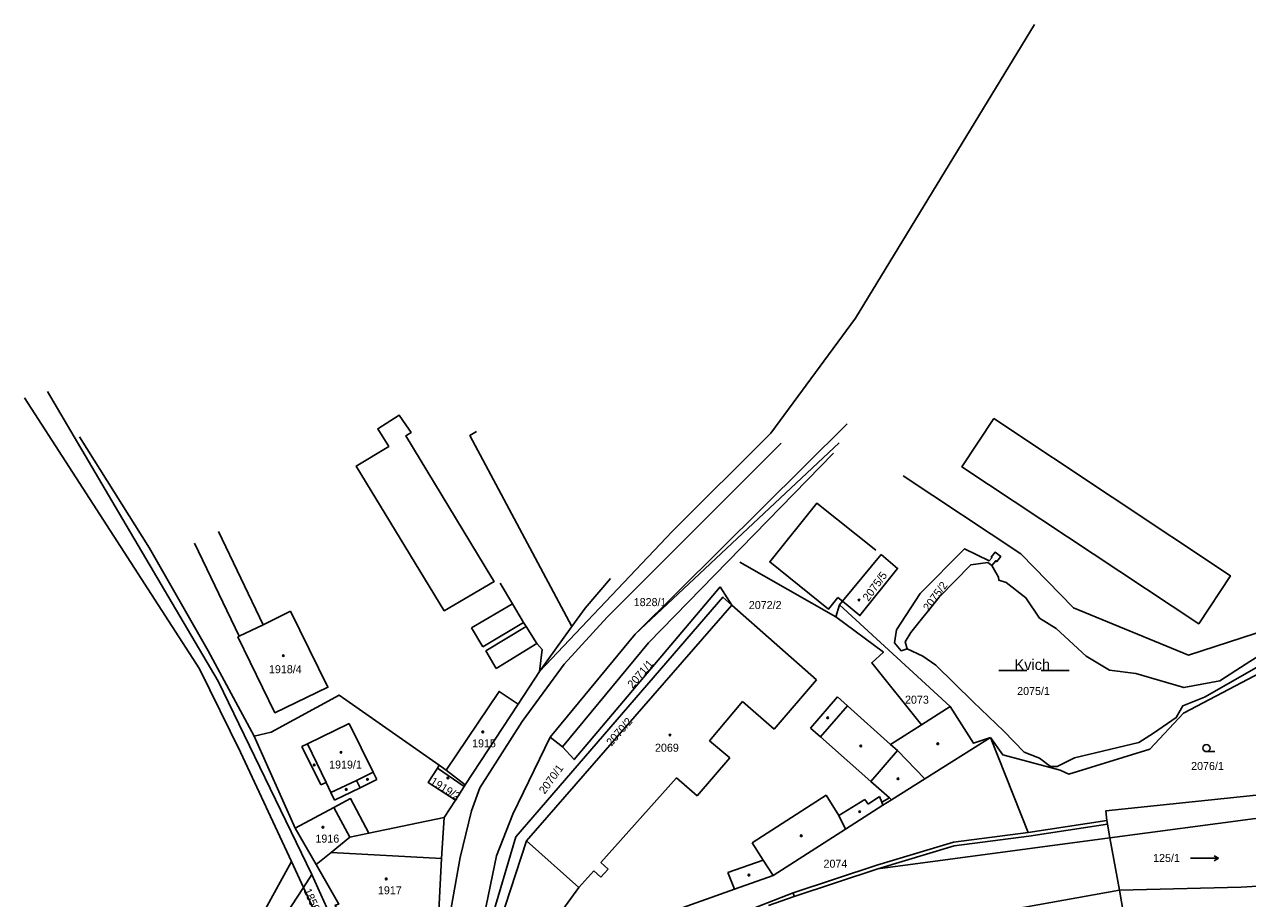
# Model space of a CAD drawing. Extents: x -783716 to -783033, y -1065203 to -1064697.
# Drawn here: x -783565.5 to -783305.8, y -1064883 to -1064697.4 of the extents above; entities that cross this region are included whole.
import ezdxf

# ---------------------------------------------------------------- set-up
doc = ezdxf.new("R2010")
doc.units = 0
for name, color, linetype in [('Budovy', 7, 'Continuous'), ('Doplňkové značky', 7, 'Continuous'), ('Doplňující texty', 7, 'Continuous'), ('Kultury', 7, 'Continuous'), ('Stromy_porost', 7, 'Continuous'), ('Značky IS', 7, 'Continuous')]:
    doc.layers.add(name, color=color, linetype=linetype)

msp = doc.modelspace()

# ---------------------------------------------------------------- linework, layer by layer
at = {"layer": 'Budovy'}
for p, q in [((-783514.83, -1064824.85), (-783524.27, -1064805.09)), ((-783529.39, -1064807.57), (-783519.89, -1064827.32)), ((-783393.24, -1064823.15), (-783413.58, -1064811.55)), ((-783391.81, -1064819.86), (-783383.6, -1064809.96)), ((-783415.27, -1064820.68), (-783417.8, -1064816.8)), ((-783391.81, -1064819.86), (-783392.77, -1064819.08)), ((-783514.83, -1064824.85), (-783509.01, -1064822.01)), ((-783393.24, -1064823.15), (-783392.46, -1064820.64)), ((-783392.46, -1064820.64), (-783391.81, -1064819.86)), ((-783368.94, -1064842.22), (-783392.46, -1064820.64)), ((-783519.89, -1064827.32), (-783514.83, -1064824.85)), ((-783520.18, -1064827.46), (-783519.89, -1064827.32)), ((-783456.16, -1064834.79), (-783449.25, -1064825.27)), ((-783456.16, -1064834.79), (-783460.7, -1064841.72)), ((-783460.7, -1064841.72), (-783471.91, -1064858.83)), ((-783508, -1064868.04), (-783516.73, -1064848.53)), ((-783352.38, -1064869), (-783360.4, -1064848.81)), ((-783508.82, -1064875.14), (-783519.64, -1064851.88)), ((-783477.44, -1064854.69), (-783475.98, -1064855.72)), ((-783475.98, -1064855.72), (-783471.91, -1064858.83)), ((-783499.8, -1064863.65), (-783508, -1064868.04)), ((-783473.99, -1064862.07), (-783476.38, -1064865.8)), ((-783503.56, -1064875.78), (-783508, -1064868.04)), ((-783523.1, -1064901.15), (-783508.82, -1064875.14)), ((-783508.82, -1064875.14), (-783506.26, -1064880.64)), ((-783506.26, -1064880.64), (-783504.45, -1064877.9)), ((-783506.26, -1064880.64), (-783502.83, -1064888))]:
    msp.add_line(p, q, dxfattribs=at)
for points in [[(-783351, -1064697.43), (-783389.01, -1064759.81), (-783407.01, -1064784.21), (-783427.95, -1064805.07), (-783448.49, -1064826.71), (-783456.16, -1064834.79)], [(-783560.59, -1064775.38), (-783546.25, -1064799.74), (-783524.35, -1064836.82), (-783504.45, -1064877.9)], [(-783519.64, -1064851.88), (-783528.32, -1064834.2), (-783565.5, -1064776.71)], [(-783484.49, -1064782.45), (-783483.39, -1064784.05), (-783484.51, -1064784.74), (-783466.28, -1064814.88), (-783465.78, -1064815.71), (-783476.35, -1064821.9), (-783495.05, -1064791.19), (-783488.16, -1064787), (-783490.49, -1064783.25), (-783485.91, -1064780.4), (-783484.49, -1064782.45)], [(-783453.88, -1064848.76), (-783435.82, -1064826.87), (-783390.82, -1064782.2)], [(-783359.63, -1064781.08), (-783309.44, -1064814.45), (-783316.16, -1064824.65), (-783366.43, -1064791.34), (-783359.63, -1064781.08)], [(-783516.73, -1064848.53), (-783526.51, -1064830.41), (-783538.93, -1064808.62), (-783553.79, -1064784.98)], [(-783449.25, -1064825.27), (-783470.93, -1064784.71), (-783469.54, -1064783.82)], [(-783378.92, -1064793.24), (-783353.96, -1064809.78), (-783342.78, -1064821.3), (-783318.3, -1064831.29), (-783298.49, -1064824.89)], [(-783392.77, -1064819.08), (-783394.74, -1064821.54), (-783407.26, -1064811.52), (-783397.23, -1064799.02), (-783384.7, -1064809.03)], [(-783360.1, -1064812.31), (-783359.24, -1064811.26), (-783359.01, -1064811.44), (-783358.2, -1064810.39), (-783359.38, -1064809.48), (-783360.21, -1064810.49), (-783360.05, -1064810.59), (-783360.62, -1064811.26), (-783365.9, -1064808.72), (-783375.28, -1064818.25), (-783380.3, -1064825.94), (-783380.77, -1064828.67), (-783379.36, -1064830.4), (-783378.03, -1064829.99)], [(-783383.6, -1064809.96), (-783380.09, -1064812.91), (-783388.1, -1064822.9), (-783391.81, -1064819.86)], [(-783360.1, -1064812.31), (-783360.93, -1064811.63), (-783364.56, -1064812.11), (-783371.25, -1064819.01), (-783377.31, -1064826.48), (-783378.51, -1064828.46), (-783378.03, -1064829.99)], [(-783298.02, -1064828.1), (-783306.05, -1064833.18), (-783311.65, -1064836.74), (-783319.29, -1064838.21), (-783322.68, -1064837.19), (-783329.49, -1064835.23), (-783335.08, -1064834.54), (-783340.03, -1064831.54), (-783346.44, -1064825.64), (-783349.95, -1064823.46), (-783352.84, -1064819.12), (-783357.07, -1064815.9), (-783358.6, -1064815.42), (-783358.65, -1064814.77), (-783360.1, -1064812.31)], [(-783417.8, -1064816.8), (-783448.79, -1064853.49), (-783451.28, -1064850.75), (-783453.88, -1064848.76)], [(-783449.25, -1064825.27), (-783446.41, -1064821.35), (-783441.05, -1064815.05)], [(-783461.16, -1064869.86), (-783417.18, -1064818.99), (-783415.27, -1064820.68)], [(-783509.01, -1064822.01), (-783501.05, -1064838.13), (-783512.33, -1064843.56), (-783520.18, -1064827.46)], [(-783464.87, -1064888.91), (-783464.59, -1064888.07), (-783458.89, -1064870.77), (-783415.27, -1064820.68)], [(-783368.94, -1064842.22), (-783375.04, -1064846.09), (-783385.6, -1064832.92), (-783383.11, -1064830.7), (-783393.24, -1064823.15)], [(-783378.03, -1064829.99), (-783374.76, -1064831.53), (-783372.01, -1064833.44), (-783364.04, -1064841.25), (-783357.52, -1064847.42), (-783353.19, -1064851.92), (-783349.93, -1064853.22), (-783347.61, -1064854.98), (-783346.18, -1064854.97), (-783342.54, -1064853.15), (-783328.86, -1064849.86), (-783325.75, -1064847.88), (-783320.94, -1064844.58), (-783319.53, -1064842.07), (-783314.96, -1064840.26), (-783304.91, -1064834.5), (-783297.7, -1064830.36)], [(-783297.44, -1064832.08), (-783319.38, -1064843.66), (-783326.57, -1064851.27), (-783343.73, -1064856.59), (-783345.55, -1064855.72), (-783357.76, -1064852.46), (-783360.4, -1064848.81)], [(-783516.73, -1064848.53), (-783513.09, -1064847.66), (-783498.65, -1064839.8), (-783477.44, -1064854.69)], [(-783475.98, -1064855.72), (-783464.73, -1064839), (-783460.7, -1064841.72)], [(-783360.4, -1064848.81), (-783364, -1064850.02), (-783368.94, -1064842.22)], [(-783467.9, -1064886.57), (-783465.25, -1064873.91), (-783461.77, -1064865.05), (-783453.88, -1064848.76)], [(-783463.71, -1064892.42), (-783459.11, -1064896.13), (-783455.45, -1064899.52), (-783437.94, -1064889.26), (-783414.73, -1064881.01), (-783406.49, -1064878.08), (-783391.14, -1064868.23), (-783383.2, -1064863.13), (-783381.42, -1064862.01), (-783374.34, -1064857.56), (-783360.4, -1064848.81)], [(-783473.99, -1064862.07), (-783479.79, -1064858.33), (-783477.82, -1064855.28), (-783477.44, -1064854.69)], [(-783471.91, -1064858.83), (-783472.14, -1064859.18), (-783473.99, -1064862.07)], [(-783285.8, -1064861.46), (-783303.98, -1064861.03), (-783335.87, -1064864.4), (-783335.67, -1064866.45), (-783352.38, -1064869)], [(-783503.56, -1064875.78), (-783500.4, -1064873.2), (-783496.43, -1064869.95), (-783499.8, -1064863.65)], [(-783476.38, -1064865.8), (-783492.34, -1064869.1), (-783496.26, -1064861.76), (-783499.8, -1064863.65)], [(-783476.38, -1064865.8), (-783476.96, -1064874.51), (-783477.75, -1064889.71), (-783481.18, -1064905.88)], [(-783223.32, -1064876.5), (-783278.18, -1064867.77), (-783285.91, -1064866.45), (-783304.09, -1064866.02), (-783335.01, -1064870.13), (-783384.26, -1064876.67), (-783402.03, -1064882.54), (-783402.29, -1064881.78)], [(-783352.38, -1064869), (-783368.2, -1064871.03), (-783384.5, -1064875.9), (-783402.29, -1064881.78)], [(-783464.87, -1064888.91), (-783466.61, -1064888.26), (-783461.16, -1064869.86)], [(-783490.48, -1064903.67), (-783499.51, -1064884.38), (-783498.76, -1064884.16), (-783503.56, -1064875.78)], [(-783504.45, -1064877.9), (-783500.04, -1064887.77), (-783502.83, -1064888)], [(-783364.93, -1064886.92), (-783332.97, -1064881.2), (-783307.17, -1064880.57), (-783287.03, -1064879.4)], [(-783511.32, -1064888.33), (-783508.83, -1064884.54), (-783506.26, -1064880.64)], [(-783402.29, -1064881.78), (-783407.72, -1064883.89), (-783423.7, -1064890.15), (-783437.08, -1064895.97), (-783447.3, -1064901.74), (-783469.27, -1064918.46), (-783474.07, -1064924.03), (-783478.28, -1064929.62)]]:
    msp.add_lwpolyline(points, dxfattribs=at)
at = {"layer": 'Doplňkové značky'}
for p, q in [((-783441.79, -1064823.28), (-783404.84, -1064786.34)), ((-783435.82, -1064826.87), (-783392.47, -1064786.22)), ((-783432.99, -1064828.7), (-783393.68, -1064788.45)), ((-783464.46, -1064816.02), (-783461.89, -1064820.41)), ((-783470.59, -1064825.54), (-783461.89, -1064820.41)), ((-783461.89, -1064820.41), (-783459.52, -1064824.37)), ((-783415.27, -1064820.68), (-783397.33, -1064836.53)), ((-783468.19, -1064829.56), (-783459.52, -1064824.37)), ((-783459.52, -1064824.37), (-783458.95, -1064825.22)), ((-783450.9, -1064833.2), (-783441.79, -1064823.28)), ((-783470.59, -1064825.54), (-783468.19, -1064829.56)), ((-783467.53, -1064830.42), (-783458.95, -1064825.22)), ((-783458.95, -1064825.22), (-783456.69, -1064828.87)), ((-783465.32, -1064834.14), (-783456.69, -1064828.87)), ((-783456.69, -1064828.87), (-783455.57, -1064830.14)), ((-783451.28, -1064850.75), (-783432.99, -1064828.7)), ((-783467.53, -1064830.42), (-783465.32, -1064834.14)), ((-783456.16, -1064834.79), (-783455.57, -1064830.14)), ((-783459.83, -1064845.42), (-783450.9, -1064833.2)), ((-783406.3, -1064847), (-783397.33, -1064836.53)), ((-783398.57, -1064846.83), (-783392.89, -1064840.19)), ((-783392.89, -1064840.19), (-783390.74, -1064842.11)), ((-783420.03, -1064849.51), (-783413.04, -1064841.14)), ((-783413.04, -1064841.14), (-783406.3, -1064847)), ((-783396.49, -1064848.65), (-783390.74, -1064842.11)), ((-783390.74, -1064842.11), (-783381.62, -1064850.26)), ((-783468.83, -1064859.49), (-783459.83, -1064845.42)), ((-783505.38, -1064850.11), (-783496.57, -1064845.8)), ((-783496.57, -1064845.8), (-783491.47, -1064856.13)), ((-783398.57, -1064846.83), (-783396.49, -1064848.65)), ((-783381.62, -1064850.26), (-783375.04, -1064846.09)), ((-783506.63, -1064850.73), (-783505.38, -1064850.11)), ((-783506.63, -1064850.73), (-783502.55, -1064858.85)), ((-783505.38, -1064850.11), (-783501.47, -1064858.33)), ((-783420.03, -1064849.51), (-783415.73, -1064853.11)), ((-783396.49, -1064848.65), (-783385.75, -1064858.12)), ((-783381.62, -1064850.26), (-783380.15, -1064851.57)), ((-783422.67, -1064861.15), (-783415.73, -1064853.11)), ((-783385.75, -1064858.12), (-783380.15, -1064851.57)), ((-783380.15, -1064851.57), (-783374.34, -1064857.56)), ((-783477.82, -1064855.28), (-783472.14, -1064859.18)), ((-783502.55, -1064858.85), (-783501.47, -1064858.33)), ((-783501.47, -1064858.33), (-783500.44, -1064860.47)), ((-783500.44, -1064860.47), (-783494.98, -1064857.96)), ((-783494.98, -1064857.96), (-783491.47, -1064856.13)), ((-783494.98, -1064857.96), (-783494.25, -1064859.48)), ((-783494.25, -1064859.48), (-783490.67, -1064857.74)), ((-783491.47, -1064856.13), (-783490.67, -1064857.74)), ((-783443.08, -1064875.37), (-783427.04, -1064857.37)), ((-783427.04, -1064857.37), (-783422.67, -1064861.15)), ((-783385.75, -1064858.12), (-783381.79, -1064861.6)), ((-783500.44, -1064860.47), (-783499.67, -1064862.11)), ((-783499.67, -1064862.11), (-783494.25, -1064859.48)), ((-783470.55, -1064864.36), (-783468.83, -1064859.49)), ((-783410.95, -1064871.18), (-783395.23, -1064861.02)), ((-783395.23, -1064861.02), (-783392.56, -1064865.33)), ((-783392.56, -1064865.33), (-783387.05, -1064861.93)), ((-783387.05, -1064861.93), (-783386.38, -1064862.95)), ((-783386.38, -1064862.95), (-783383.92, -1064861.34)), ((-783383.92, -1064861.34), (-783383.43, -1064862.54)), ((-783383.43, -1064862.54), (-783381.79, -1064861.6)), ((-783383.43, -1064862.54), (-783383.2, -1064863.13)), ((-783381.79, -1064861.6), (-783381.42, -1064862.01)), ((-783472.96, -1064874.3), (-783470.55, -1064864.36)), ((-783392.56, -1064865.33), (-783391.14, -1064868.23)), ((-783335.67, -1064866.45), (-783335.55, -1064867.23)), ((-783352.25, -1064869.78), (-783335.55, -1064867.23)), ((-783335.55, -1064867.23), (-783335.01, -1064870.13)), ((-783496.43, -1064869.95), (-783492.34, -1064869.1)), ((-783458.89, -1064870.77), (-783447.79, -1064880.65)), ((-783410.95, -1064871.18), (-783408.61, -1064874.84)), ((-783368.09, -1064871.83), (-783352.25, -1064869.78)), ((-783335.01, -1064870.13), (-783332.97, -1064881.2)), ((-783500.4, -1064873.2), (-783476.96, -1064874.51)), ((-783384.26, -1064876.67), (-783368.09, -1064871.83)), ((-783478.7, -1064906.42), (-783472.96, -1064874.3)), ((-783443.1, -1064878.47), (-783441.55, -1064876.73)), ((-783443.08, -1064875.37), (-783441.55, -1064876.73)), ((-783416.14, -1064877.45), (-783408.61, -1064874.84)), ((-783408.61, -1064874.84), (-783406.49, -1064878.08)), ((-783447.79, -1064880.65), (-783444.63, -1064877.11)), ((-783444.63, -1064877.11), (-783443.1, -1064878.47)), ((-783416.14, -1064877.45), (-783414.73, -1064881.01)), ((-783459.11, -1064896.13), (-783447.79, -1064880.65)), ((-783332.97, -1064881.2), (-783332.16, -1064886.15)), ((-783407.53, -1064884.46), (-783402.03, -1064882.54))]:
    msp.add_line(p, q, dxfattribs=at)
at = {"layer": 'Doplňující texty'}
for centre in [(-783388.3, -1064819.62), (-783510.53, -1064831.42), (-783394.95, -1064844.61), (-783468.18, -1064847.6), (-783428.41, -1064848.28), (-783387.92, -1064850.62), (-783371.57, -1064850.14), (-783498.29, -1064851.96), (-783503.98, -1064854.62), (-783492.67, -1064857.68), (-783475.59, -1064857.38), (-783380.02, -1064857.57), (-783497.18, -1064859.83), (-783388.16, -1064864.53), (-783502.14, -1064867.84), (-783400.56, -1064869.67), (-783488.69, -1064878.82), (-783411.67, -1064878.02)]:
    msp.add_circle(centre, 0.175, dxfattribs=at)
at = {"layer": 'Kultury'}
for p, q in [((-783358.63, -1064834.57), (-783352.63, -1064834.57)), ((-783349.63, -1064834.57), (-783343.63, -1064834.57)), ((-783314.51, -1064851.8), (-783312.76, -1064851.8)), ((-783311.93, -1064874.45), (-783312.91, -1064873.95)), ((-783317.93, -1064874.45), (-783311.93, -1064874.45)), ((-783311.93, -1064874.45), (-783312.91, -1064874.95))]:
    msp.add_line(p, q, dxfattribs=at)
msp.add_circle((-783314.51, -1064851.05), 0.75, dxfattribs=at)

# ---------------------------------------------------------------- texts
at = {"layer": 'Stromy_porost'}
msp.add_text('Kvich', height=2.3, dxfattribs=at).set_placement((-783355.25, -1064834.47))
at = {"layer": 'Značky IS'}
for s, rotation, p in [('2075/5', 54, (-783386.29, -1064820.01)), ('2075/2', 54, (-783373.47, -1064822.12)), ('2071/1', 49, (-783436.36, -1064838.48)), ('2070/2', 49, (-783440.84, -1064850.75)), ('2070/1', 54, (-783455.03, -1064860.95)), ('1919/2', 328, (-783479.5, -1064858.55)), ('1856/9', 294, (-783506.27, -1064881.28))]:
    msp.add_text(s, height=1.7, rotation=rotation, dxfattribs=at).set_placement(p)
for s, p in [('1828/1', (-783436.13, -1064820.91)), ('2072/2', (-783411.69, -1064821.53)), ('1918/4', (-783513.58, -1064835.15)), ('2073', (-783378.52, -1064841.62)), ('2075/1', (-783354.71, -1064839.78)), ('1915', (-783470.45, -1064850.89)), ('2069', (-783431.61, -1064851.82)), ('1919/1', (-783500.81, -1064855.4)), ('2076/1', (-783317.77, -1064855.7)), ('1916', (-783503.72, -1064871.11)), ('125/1', (-783325.84, -1064875.22)), ('2074', (-783395.83, -1064876.44)), ('1917', (-783490.44, -1064882.09))]:
    msp.add_text(s, height=1.7, dxfattribs=at).set_placement(p)

doc.saveas('drawing.dxf')
